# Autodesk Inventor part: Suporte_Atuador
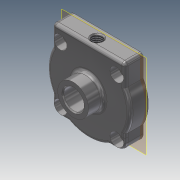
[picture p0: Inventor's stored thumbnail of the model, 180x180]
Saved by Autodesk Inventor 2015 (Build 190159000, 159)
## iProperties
Created: 2015-04
Part Number: Suporte_Atuador
Material: Steel, Carbon
Document SubType Name: Modeling
Designer: TREINA6
Density: 7.85 g/cm^3
Appearance: Semi-Polished
Author: TREINA6
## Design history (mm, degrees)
workplane "Work Plane1"
sketch "Sketch1"
  geometry: L1 (32.5, -27.5)-(32.5, -18.708) reference; L2 (32.5, 18.708)-(32.5, 27.5) reference; L3 (27.5, 32.5)-(18.708, 32.5) reference; L4 (-18.708, 32.5)-(-27.5, 32.5) reference; L5 (-32.5, 27.5)-(-32.5, 18.708) reference; L6 (-32.5, -18.708)-(-32.5, -27.5) reference; L7 (-27.5, -32.5)-(-18.708, -32.5) reference; L8 (18.708, -32.5)-(27.5, -32.5) reference; L9 (35.5, -19.494)-(35.5, -27.5); L10 (27.5, -35.5)-(19.494, -35.5); L11 (-19.494, -35.5)-(-27.5, -35.5); L12 (-35.5, -27.5)-(-35.5, -19.494); L13 (-35.5, 19.494)-(-35.5, 27.5); L14 (-27.5, 35.5)-(-19.494, 35.5); L15 (19.494, 35.5)-(27.5, 35.5); L16 (35.5, 27.5)-(35.5, 19.494); C1 r 3.324 at (27.5, -27.5) reference; C2 r 3.324 at (-27.5, -27.5) reference; C3 r 3.324 at (-27.5, 27.5) reference; C4 r 3.324 at (27.5, 27.5) reference; C5 r 25 at (0, 0) reference; A1 r 5 centre (27.5, -27.5) between (27.5, -32.5) and (32.5, -27.5) reference; A2 r 37.5 centre (0, 0) between (32.5, -18.708) and (32.5, 18.708) reference; A3 r 5 centre (27.5, 27.5) between (32.5, 27.5) and (27.5, 32.5) reference; A4 r 37.5 centre (0, 0) between (18.708, 32.5) and (-18.708, 32.5) reference; A5 r 5 centre (-27.5, 27.5) between (-27.5, 32.5) and (-32.5, 27.5) reference; A6 r 37.5 centre (0, 0) between (-32.5, 18.708) and (-32.5, -18.708) reference; A7 r 5 centre (-27.5, -27.5) between (-32.5, -27.5) and (-27.5, -32.5) reference; A8 r 37.5 centre (0, 0) between (-18.708, -32.5) and (18.708, -32.5) reference; A9 r 40.5 centre (0, 0) between (35.5, -19.494) and (35.5, 19.494); A10 r 8 centre (27.5, -27.5) between (27.5, -35.5) and (35.5, -27.5); A11 r 40.5 centre (0, 0) between (-19.494, -35.5) and (19.494, -35.5); A12 r 8 centre (-27.5, -27.5) between (-35.5, -27.5) and (-27.5, -35.5); A13 r 40.5 centre (0, 0) between (-35.5, 19.494) and (-35.5, -19.494); A14 r 8 centre (-27.5, 27.5) between (-27.5, 35.5) and (-35.5, 27.5); A15 r 40.5 centre (0, 0) between (19.494, 35.5) and (-19.494, 35.5); A16 r 8 centre (27.5, 27.5) between (35.5, 27.5) and (27.5, 35.5); 1 further point
  constraints: 16 end point, 16 point on circle, 8 centre point, 15 other
  dimensions: "d0" = 3 radial gap between concentric circles of A2 A9
extrude "Extrusion1" new body sketch "Sketch1" distance "d1" = 15; taper "d3" = 0 deg; dims "d2" = 3, "d4" = 0
sketch "Sketch2"
  geometry: L1 (27.5, -32.5)-(18.708, -32.5) reference; L2 (-18.708, -32.5)-(-27.5, -32.5) reference; L3 (-32.5, -27.5)-(-32.5, -18.708) reference; L4 (-32.5, 18.708)-(-32.5, 27.5) reference; L5 (-27.5, 32.5)-(-18.708, 32.5) reference; L6 (18.708, 32.5)-(27.5, 32.5) reference; L7 (32.5, 27.5)-(32.5, 18.708) reference; L8 (32.5, -18.708)-(32.5, -27.5) reference; L9 (35.5, 19.494)-(35.5, 27.5) reference; L10 (27.5, 35.5)-(19.494, 35.5) reference; L11 (-19.494, 35.5)-(-27.5, 35.5) reference; L12 (-35.5, 27.5)-(-35.5, 19.494) reference; L13 (-35.5, -19.494)-(-35.5, -27.5) reference; L14 (-27.5, -35.5)-(-19.494, -35.5) reference; L15 (19.494, -35.5)-(27.5, -35.5) reference; L16 (35.5, -27.5)-(35.5, -19.494) reference; A1 r 37.5 centre (0, 0) between (-18.708, -32.5) and (18.708, -32.5) reference; A2 r 5 centre (-27.5, -27.5) between (-32.5, -27.5) and (-27.5, -32.5) reference; A3 r 37.5 centre (0, 0) between (-32.5, 18.708) and (-32.5, -18.708) reference; A4 r 5 centre (-27.5, 27.5) between (-27.5, 32.5) and (-32.5, 27.5) reference; A5 r 37.5 centre (0, 0) between (18.708, 32.5) and (-18.708, 32.5) reference; A6 r 5 centre (27.5, 27.5) between (32.5, 27.5) and (27.5, 32.5) reference; A7 r 37.5 centre (0, 0) between (32.5, -18.708) and (32.5, 18.708) reference; A8 r 5 centre (27.5, -27.5) between (27.5, -32.5) and (32.5, -27.5) reference; A9 r 40.5 centre (0, 0) between (35.5, -19.494) and (35.5, 19.494) reference; A10 r 8 centre (27.5, 27.5) between (35.5, 27.5) and (27.5, 35.5) reference; A11 r 40.5 centre (0, 0) between (19.494, 35.5) and (-19.494, 35.5) reference; A12 r 8 centre (-27.5, 27.5) between (-27.5, 35.5) and (-35.5, 27.5) reference; A13 r 40.5 centre (0, 0) between (-35.5, 19.494) and (-35.5, -19.494) reference; A14 r 8 centre (-27.5, -27.5) between (-35.5, -27.5) and (-27.5, -35.5) reference; A15 r 40.5 centre (0, 0) between (-19.494, -35.5) and (19.494, -35.5) reference; A16 r 8 centre (27.5, -27.5) between (27.5, -35.5) and (35.5, -27.5) reference; 1 further point
extrude "Extrusion2" join sketch "Sketch2" distance "d5" = 15; taper "d6" = 0 deg
hole "Hole1" diameter "d9" = 8.5; stored, may be unused: countersink angle "d13" = 82 deg, drill point angle "d15" = 118 deg; dims "d10" = 19.05, "d11" = 13, "d12" = 8.5, "d14" = 25.4, "d51" = 10, "d52" = 10
pattern_circular "Circular Pattern1" dims angle "d17" = 360 deg
hole "Hole2" diameter "d21" = 20; stored, may be unused: countersink angle "d25" = 82 deg, drill point angle "d27" = 118 deg; dims "d22" = 19.05, "d23" = 13, "d24" = 5, "d26" = 25.4, "d28" = 25.4, "d29" = 25.4
sketch "Sketch3"
  geometry: C1 r 10 at (0, 0) reference; C2 r 15 at (0, 0); 1 further point
  constraints: 1 centre point
  dimensions: "d30" = 5 radial gap between concentric circles of C1 C2
extrude "Extrusion3" join sketch "Sketch3" distance "d31" = 15; taper "d32" = 0 deg
sketch "Sketch4"
  geometry: L1 (35.5, 19.494)-(35.5, 27.5) reference; L2 (27.5, 35.5)-(19.494, 35.5) reference; L3 (-19.494, 35.5)-(-27.5, 35.5) reference; L4 (-35.5, 27.5)-(-35.5, 19.494) reference; L5 (-35.5, -19.494)-(-35.5, -27.5) reference; L6 (-27.5, -35.5)-(-19.494, -35.5) reference; L7 (19.494, -35.5)-(27.5, -35.5) reference; L8 (35.5, -27.5)-(35.5, -19.494) reference; L9 (-35.5, 27.5)-(-35.5, 40.5); L10 (-35.5, 40.5)-(0, 40.5); L11 (0, 40.5)-(35.5, 40.5); L12 (35.5, 40.5)-(35.5, 27.5); C1 r 15 at (0, 0) reference; C2 r 6.5 at (27.5, 27.5) reference; C3 r 6.5 at (27.5, -27.5) reference; C4 r 6.5 at (-27.5, -27.5) reference; C5 r 6.5 at (-27.5, 27.5) reference; A1 r 40.5 centre (0, 0) between (35.5, -19.494) and (35.5, 19.494) reference; A2 r 8 centre (27.5, 27.5) between (35.5, 27.5) and (27.5, 35.5) reference; A3 r 40.5 centre (0, 0) between (19.494, 35.5) and (-19.494, 35.5) reference; A4 r 8 centre (-27.5, 27.5) between (-27.5, 35.5) and (-35.5, 27.5) reference; A5 r 40.5 centre (0, 0) between (-35.5, 19.494) and (-35.5, -19.494) reference; A6 r 8 centre (-27.5, -27.5) between (-35.5, -27.5) and (-27.5, -35.5) reference; A7 r 40.5 centre (0, 0) between (-19.494, -35.5) and (19.494, -35.5) reference; A8 r 8 centre (27.5, -27.5) between (27.5, -35.5) and (35.5, -27.5) reference; A9 r 40.5 centre (0, 0) between (19.494, 35.5) and (-19.494, 35.5) reference; A10 r 8 centre (27.5, 27.5) between (35.5, 27.5) and (27.5, 35.5) reference; 1 further point
  constraints: 8 end point, 3 tangent, 2 point on circle, 1 perpendicular, 1 point on line, 1 vertical
extrude "Extrusion4" join sketch "Sketch4" stored distance "d38" = 8; taper "d39" = 0 deg
fillet "Fillet1" dims "d33" = 3.175
fillet "Fillet2" dims "d34" = 3.175
chamfer "Chamfer1" distance "d35" = 1; stored, may be unused: second distance "d36" = 2, angle "d37" = 45 deg
sketch "Sketch5"
  geometry: L1 (-3.175, 14.825)-(-3.175, 0) reference; L2 (13.617, 11.825)-(51.033, 11.825) reference; 3 further points
  constraints: 1 midpoint, 1 vertical alignment
  dimensions: "d47" = 6.5 distance from line of L2 point (32.325, 5.325)
hole "Hole3" sketch "Sketch5" at (32.325, 5.325) diameter "d40" = 10.106; stored, may be unused: countersink angle "d44" = 82 deg, drill point angle "d46" = 118 deg; dims "d41" = 24, "d42" = 13, "d43" = 5, "d45" = 36.55
chamfer "Chamfer2" distance "d48" = 1; stored, may be unused: second distance "d49" = 2, angle "d50" = 45 deg
body "Solid1"
node "Reference1"
node "Projected Loop1"
node "Projected Loop2"
